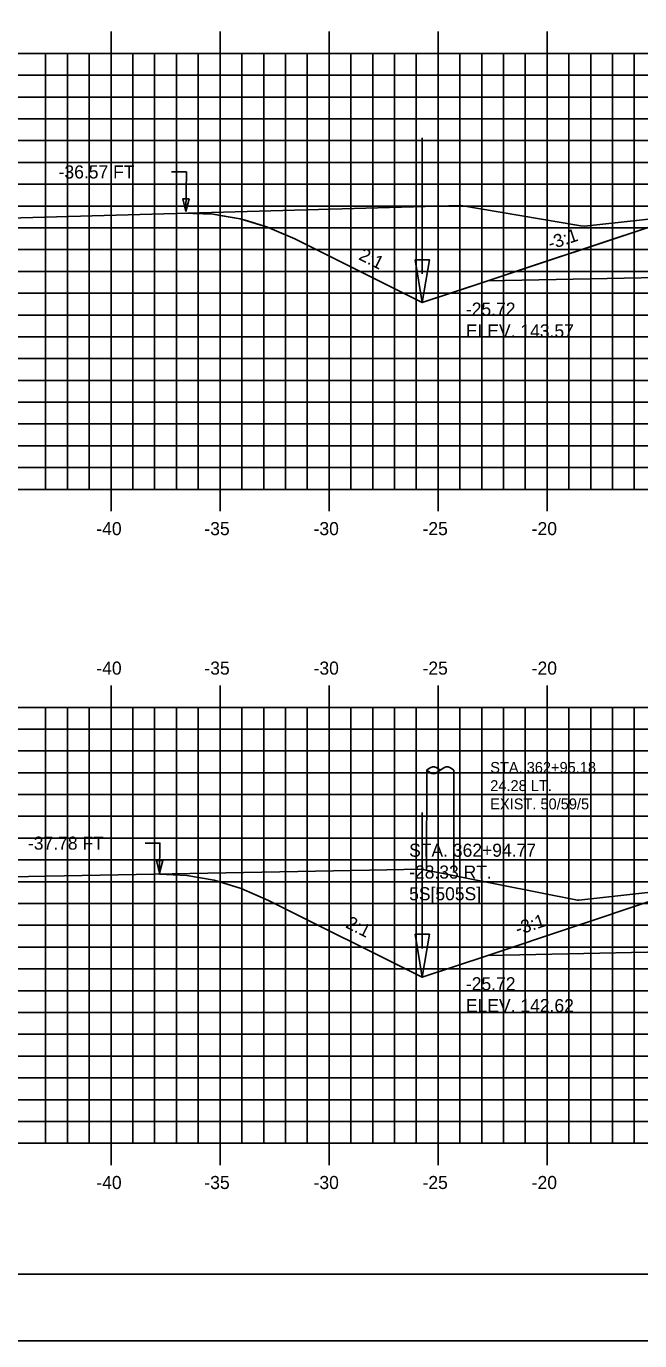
# Model space of a CAD drawing. Extents: x 1146968 to 1147138, y 608981 to 609091.
# Drawn here: x 1147007.3 to 1147035.4, y 608981.3 to 609041.6 of the extents above; entities that cross this region are included whole.
import ezdxf

# ---------------------------------------------------------------- set-up
doc = ezdxf.new("R2010")
doc.units = 0
for name, color, linetype in [('ANNOTATION', 7, 'Continuous'), ('BORDER', 7, 'Continuous'), ('D_Drainage_Ditch_Line', 7, 'Continuous'), ('D_Roadway_SlopeLines', 7, 'Continuous'), ('D_Roadway_SubGrade', 7, 'Continuous'), ('D_Text_Monospaced', 7, 'Continuous'), ('D_Text_Standard', 7, 'Continuous'), ('H_V ANNOTATION', 7, 'Continuous'), ('MAJOR', 7, 'Continuous'), ('MINOR', 7, 'Continuous'), ('PLOT BOUNDARY', 7, 'Continuous'), ('S_Roadway_Centerline', 7, 'Continuous'), ('S_Utilities_Pole_Power', 7, 'Continuous')]:
    doc.layers.add(name, color=color, linetype=linetype)

msp = doc.modelspace()

# ---------------------------------------------------------------- linework, layer by layer
for points in [[(1147014.611, 609033.01), (1147014.936, 609032.998), (1147015.861, 609032.963), (1147016.186, 609032.907), (1147017.111, 609032.75), (1147017.436, 609032.652), (1147018.361, 609032.373), (1147018.686, 609032.232), (1147019.611, 609031.83), (1147021.137, 609031.067), (1147025.46, 609028.906), (1147027.679, 609029.645), (1147028.46, 609029.906), (1147030.469, 609030.576), (1147036.183, 609032.48)], [(1147013.409, 609002.682), (1147014.659, 609002.625), (1147015.909, 609002.405), (1147017.159, 609002.023), (1147018.409, 609001.479), (1147025.46, 608997.953), (1147028.46, 608998.953), (1147036.183, 609001.528), (1147036.184, 609001.528), (1147040.184, 609001.688), (1147051.184, 609001.908), (1147062.184, 609001.688), (1147066.184, 609001.528), (1147071.549, 609001.42)]]:
    msp.add_lwpolyline(points)
at = {"layer": 'BORDER'}
msp.add_lwpolyline([(1146976.185, 608984.335), (1147136.185, 608984.335), (1147136.185, 609089.335), (1146976.185, 609089.335)], close=True, dxfattribs=at)
at = {"layer": 'D_Drainage_Ditch_Line'}
for p, q in [((1147025.46, 609030.218), (1147025.46, 609036.461)), ((1147025.46, 608999.265), (1147025.46, 609005.509))]:
    msp.add_line(p, q, dxfattribs=at)
for points in [[(1147025.132, 609030.874), (1147025.788, 609030.874), (1147025.46, 609028.906)], [(1147025.132, 608999.922), (1147025.788, 608999.922), (1147025.46, 608997.953)]]:
    msp.add_lwpolyline(points, close=True, dxfattribs=at)
at = {"layer": 'D_Roadway_SlopeLines'}
for points in [[(1147025.46, 609028.906), (1147019.611, 609031.83), (1147018.361, 609032.373), (1147017.111, 609032.75), (1147015.861, 609032.963), (1147014.611, 609033.01)], [(1147028.46, 609029.906), (1147025.46, 609028.906)], [(1147025.46, 608997.953), (1147018.409, 609001.479), (1147017.159, 609002.023), (1147015.909, 609002.405), (1147014.659, 609002.625), (1147013.409, 609002.682)], [(1147028.46, 608998.953), (1147025.46, 608997.953)]]:
    msp.add_lwpolyline(points, dxfattribs=at)
at = {"layer": 'D_Roadway_SubGrade'}
for points in [[(1147040.184, 609032.223), (1147040.184, 609032.39), (1147036.184, 609032.23), (1147036.184, 609032.48), (1147036.183, 609032.48), (1147028.46, 609029.906), (1147040.184, 609030.14)], [(1147040.184, 609001.271), (1147040.184, 609001.438), (1147036.184, 609001.278), (1147036.184, 609001.528), (1147036.183, 609001.528), (1147028.46, 608998.953), (1147040.184, 608999.188)]]:
    msp.add_lwpolyline(points, close=True, dxfattribs=at)
at = {"layer": 'D_Text_Standard'}
for points in [[(1147014.611, 609033.08), (1147014.637, 609034.9), (1147013.957, 609034.9)], [(1147013.409, 609002.729), (1147013.423, 609004.106), (1147012.743, 609004.106)]]:
    msp.add_lwpolyline(points, dxfattribs=at)
for points in [[(1147014.611, 609033.08), (1147014.474, 609033.664), (1147014.765, 609033.66)], [(1147013.409, 609002.729), (1147013.269, 609003.312), (1147013.56, 609003.309)]]:
    msp.add_lwpolyline(points, close=True, dxfattribs=at)
at = {"layer": 'MAJOR'}
for p, q in [((1147011.184, 609041.337), (1147011.184, 609040.335)), ((1147016.184, 609041.337), (1147016.184, 609040.335)), ((1147021.184, 609041.337), (1147021.184, 609040.335)), ((1147026.184, 609041.337), (1147026.184, 609040.335)), ((1147031.184, 609041.337), (1147031.184, 609040.335)), ((1146981.184, 609040.335), (1147121.184, 609040.335)), ((1146981.184, 609040.335), (1147121.184, 609040.335)), ((1147011.184, 609020.335), (1147011.184, 609040.335)), ((1147016.184, 609020.335), (1147016.184, 609040.335)), ((1147021.184, 609020.335), (1147021.184, 609040.335)), ((1147026.184, 609020.335), (1147026.184, 609040.335)), ((1147031.184, 609020.335), (1147031.184, 609040.335)), ((1146981.184, 609035.335), (1147121.184, 609035.335)), ((1146981.184, 609030.335), (1147121.184, 609030.335)), ((1146981.184, 609025.335), (1147121.184, 609025.335)), ((1146981.184, 609020.335), (1147121.184, 609020.335)), ((1146981.184, 609020.335), (1147121.184, 609020.335)), ((1147011.184, 609019.333), (1147011.184, 609020.335)), ((1147016.184, 609019.333), (1147016.184, 609020.335)), ((1147021.184, 609019.333), (1147021.184, 609020.335)), ((1147026.184, 609019.333), (1147026.184, 609020.335)), ((1147031.184, 609019.333), (1147031.184, 609020.335)), ((1147011.184, 609011.337), (1147011.184, 609010.335)), ((1147016.184, 609011.337), (1147016.184, 609010.335)), ((1147021.184, 609011.337), (1147021.184, 609010.335)), ((1147026.184, 609011.337), (1147026.184, 609010.335)), ((1147031.184, 609011.337), (1147031.184, 609010.335)), ((1146981.184, 609010.335), (1147121.184, 609010.335)), ((1146981.184, 609010.335), (1147121.184, 609010.335)), ((1147011.184, 608990.335), (1147011.184, 609010.335)), ((1147016.184, 608990.335), (1147016.184, 609010.335)), ((1147021.184, 608990.335), (1147021.184, 609010.335)), ((1147026.184, 608990.335), (1147026.184, 609010.335)), ((1147031.184, 608990.335), (1147031.184, 609010.335)), ((1146981.184, 609005.335), (1147121.184, 609005.335)), ((1146981.184, 609000.335), (1147121.184, 609000.335)), ((1146981.184, 608995.335), (1147121.184, 608995.335)), ((1146981.184, 608990.335), (1147121.184, 608990.335)), ((1146981.184, 608990.335), (1147121.184, 608990.335)), ((1147011.184, 608989.333), (1147011.184, 608990.335)), ((1147016.184, 608989.333), (1147016.184, 608990.335)), ((1147021.184, 608989.333), (1147021.184, 608990.335)), ((1147026.184, 608989.333), (1147026.184, 608990.335)), ((1147031.184, 608989.333), (1147031.184, 608990.335))]:
    msp.add_line(p, q, dxfattribs=at)
at = {"layer": 'MINOR'}
for p, q in [((1147008.184, 609020.335), (1147008.184, 609040.335)), ((1147009.184, 609020.335), (1147009.184, 609040.335)), ((1147010.184, 609020.335), (1147010.184, 609040.335)), ((1147012.184, 609020.335), (1147012.184, 609040.335)), ((1147013.184, 609020.335), (1147013.184, 609040.335)), ((1147014.184, 609020.335), (1147014.184, 609040.335)), ((1147015.184, 609020.335), (1147015.184, 609040.335)), ((1147017.184, 609020.335), (1147017.184, 609040.335)), ((1147018.184, 609020.335), (1147018.184, 609040.335)), ((1147019.184, 609020.335), (1147019.184, 609040.335)), ((1147020.184, 609020.335), (1147020.184, 609040.335)), ((1147022.184, 609020.335), (1147022.184, 609040.335)), ((1147023.184, 609020.335), (1147023.184, 609040.335)), ((1147024.184, 609020.335), (1147024.184, 609040.335)), ((1147025.184, 609020.335), (1147025.184, 609040.335)), ((1147027.184, 609020.335), (1147027.184, 609040.335)), ((1147028.184, 609020.335), (1147028.184, 609040.335)), ((1147029.184, 609020.335), (1147029.184, 609040.335)), ((1147030.184, 609020.335), (1147030.184, 609040.335)), ((1147032.184, 609020.335), (1147032.184, 609040.335)), ((1147033.184, 609020.335), (1147033.184, 609040.335)), ((1147034.184, 609020.335), (1147034.184, 609040.335)), ((1147035.184, 609020.335), (1147035.184, 609040.335)), ((1146981.184, 609039.335), (1147121.184, 609039.335)), ((1146981.184, 609038.335), (1147121.184, 609038.335)), ((1146981.184, 609037.335), (1147121.184, 609037.335)), ((1146981.184, 609036.335), (1147121.184, 609036.335)), ((1146981.184, 609034.335), (1147121.184, 609034.335)), ((1146981.184, 609033.335), (1147121.184, 609033.335)), ((1146981.184, 609032.335), (1147121.184, 609032.335)), ((1146981.184, 609031.335), (1147121.184, 609031.335)), ((1146981.184, 609029.335), (1147121.184, 609029.335)), ((1146981.184, 609028.335), (1147121.184, 609028.335)), ((1146981.184, 609027.335), (1147121.184, 609027.335)), ((1146981.184, 609026.335), (1147121.184, 609026.335)), ((1146981.184, 609024.335), (1147121.184, 609024.335)), ((1146981.184, 609023.335), (1147121.184, 609023.335)), ((1146981.184, 609022.335), (1147121.184, 609022.335)), ((1146981.184, 609021.335), (1147121.184, 609021.335)), ((1147008.184, 608990.335), (1147008.184, 609010.335)), ((1147009.184, 608990.335), (1147009.184, 609010.335)), ((1147010.184, 608990.335), (1147010.184, 609010.335)), ((1147012.184, 608990.335), (1147012.184, 609010.335)), ((1147013.184, 608990.335), (1147013.184, 609010.335)), ((1147014.184, 608990.335), (1147014.184, 609010.335)), ((1147015.184, 608990.335), (1147015.184, 609010.335)), ((1147017.184, 608990.335), (1147017.184, 609010.335)), ((1147018.184, 608990.335), (1147018.184, 609010.335)), ((1147019.184, 608990.335), (1147019.184, 609010.335)), ((1147020.184, 608990.335), (1147020.184, 609010.335)), ((1147022.184, 608990.335), (1147022.184, 609010.335)), ((1147023.184, 608990.335), (1147023.184, 609010.335)), ((1147024.184, 608990.335), (1147024.184, 609010.335)), ((1147025.184, 608990.335), (1147025.184, 609010.335)), ((1147027.184, 608990.335), (1147027.184, 609010.335)), ((1147028.184, 608990.335), (1147028.184, 609010.335)), ((1147029.184, 608990.335), (1147029.184, 609010.335)), ((1147030.184, 608990.335), (1147030.184, 609010.335)), ((1147032.184, 608990.335), (1147032.184, 609010.335)), ((1147033.184, 608990.335), (1147033.184, 609010.335)), ((1147034.184, 608990.335), (1147034.184, 609010.335)), ((1147035.184, 608990.335), (1147035.184, 609010.335)), ((1146981.184, 609009.335), (1147121.184, 609009.335)), ((1146981.184, 609008.335), (1147121.184, 609008.335)), ((1146981.184, 609007.335), (1147121.184, 609007.335)), ((1146981.184, 609006.335), (1147121.184, 609006.335)), ((1146981.184, 609004.335), (1147121.184, 609004.335)), ((1146981.184, 609003.335), (1147121.184, 609003.335)), ((1146981.184, 609002.335), (1147121.184, 609002.335)), ((1146981.184, 609001.335), (1147121.184, 609001.335)), ((1146981.184, 608999.335), (1147121.184, 608999.335)), ((1146981.184, 608998.335), (1147121.184, 608998.335)), ((1146981.184, 608997.335), (1147121.184, 608997.335)), ((1146981.184, 608996.335), (1147121.184, 608996.335)), ((1146981.184, 608994.335), (1147121.184, 608994.335)), ((1146981.184, 608993.335), (1147121.184, 608993.335)), ((1146981.184, 608992.335), (1147121.184, 608992.335)), ((1146981.184, 608991.335), (1147121.184, 608991.335))]:
    msp.add_line(p, q, dxfattribs=at)
at = {"layer": 'PLOT BOUNDARY'}
msp.add_lwpolyline([(1146968.091, 608981.276), (1147138.091, 608981.276), (1147138.091, 609091.276), (1146968.091, 609091.276)], close=True, dxfattribs=at)
at = {"layer": 'S_Roadway_Centerline'}
for points in [[(1146996.648, 609032.505), (1147017.432, 609033.089), (1147027.223, 609033.36), (1147032.732, 609032.426), (1147032.902, 609032.414), (1147036.544, 609032.814)], [(1146999.147, 609002.419), (1147023.036, 609002.861), (1147025.413, 609002.903), (1147032.582, 609001.491), (1147032.634, 609001.482), (1147036.91, 609001.96)]]:
    msp.add_lwpolyline(points, dxfattribs=at)
at = {"layer": 'S_Utilities_Pole_Power'}
for p, q in [((1147025.659, 609007.449), (1147025.815, 609007.559)), ((1147025.659, 609002.83), (1147025.663, 609007.449)), ((1147025.815, 609007.338), (1147025.659, 609007.449)), ((1147026.128, 609007.559), (1147026.285, 609007.449)), ((1147026.285, 609007.449), (1147026.128, 609007.338)), ((1147026.441, 609007.559), (1147026.285, 609007.449)), ((1147026.909, 609007.449), (1147026.753, 609007.559)), ((1147026.909, 609002.83), (1147026.913, 609007.449))]:
    msp.add_line(p, q, dxfattribs=at)
for centre, start, end in [((1147025.972, 609007.339), 90, 125.26439), ((1147025.972, 609007.339), 54.73561, 90), ((1147026.597, 609007.339), 90, 125.26439), ((1147026.597, 609007.339), 54.73561, 90), ((1147025.972, 609007.56), 234.73561, 270), ((1147025.972, 609007.56), 270, 305.26439)]:
    msp.add_arc(centre, 0.271, start, end, dxfattribs=at)

# ---------------------------------------------------------------- texts
at = {"layer": 'ANNOTATION'}
for s, rotation, p in [('-3:1', 18.43478, (1147031.339, 609031.319)), ('2:1', 333.43495, (1147022.502, 609030.902)), ('-3:1', 18.43482, (1147029.839, 608999.867)), ('2:1', 333.43495, (1147021.901, 609000.25))]:
    msp.add_text(s, height=0.6, rotation=rotation, dxfattribs=at).set_placement(p)
at = {"layer": 'D_Text_Monospaced'}
for s, height, p in [('STA. 362+95.18', 0.49998, (1147028.576, 609007.328)), ('24.28 LT.', 0.5, (1147028.576, 609006.494)), ('EXIST. 50/59/5', 0.49998, (1147028.576, 609005.654))]:
    msp.add_text(s, height=height, dxfattribs=at).set_placement(p)
at = {"layer": 'D_Text_Standard'}
for s, p in [('-36.57 FT', (1147008.78, 609034.6)), ('-25.72', (1147027.46, 609028.306)), ('ELEV. 143.57', (1147027.46, 609027.304)), ('-37.78 FT', (1147007.374, 609003.806)), ('STA. 362+94.77', (1147024.855, 609003.48)), ('-28.33 RT.', (1147024.855, 609002.478)), ('5S[505S] ', (1147024.855, 609001.482)), ('-25.72', (1147027.46, 608997.353)), ('ELEV. 142.62', (1147027.46, 608996.351))]:
    msp.add_text(s, height=0.6, dxfattribs=at).set_placement(p)
at = {"layer": 'H_V ANNOTATION'}
for s, p in [('-40', (1147010.51, 609018.235)), ('-35', (1147015.465, 609018.235)), ('-30', (1147020.473, 609018.235)), ('-25', (1147025.47, 609018.235)), ('-20', (1147030.478, 609018.235)), ('-40', (1147010.51, 609011.835)), ('-35', (1147015.465, 609011.835)), ('-30', (1147020.473, 609011.835)), ('-25', (1147025.47, 609011.835)), ('-20', (1147030.478, 609011.835)), ('-40', (1147010.51, 608988.235)), ('-35', (1147015.465, 608988.235)), ('-30', (1147020.473, 608988.235)), ('-25', (1147025.47, 608988.235)), ('-20', (1147030.478, 608988.235))]:
    msp.add_text(s, height=0.6, dxfattribs=at).set_placement(p)

doc.saveas('drawing.dxf')
